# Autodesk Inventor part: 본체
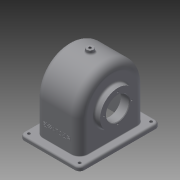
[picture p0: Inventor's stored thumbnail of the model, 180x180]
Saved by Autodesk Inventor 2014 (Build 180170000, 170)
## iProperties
Created: 2016-01
Part Number: 본체
Material: 일반
Document SubType Name: Modeling
Designer: USER
Density: 1 g/cm^3
Appearance: 기본값
Author: USER
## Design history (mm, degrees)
sketch "스케치1"
  geometry: L1 (-57, 0)-(-57, -57); L2 (-57, -57)-(57, -57); L3 (57, 0)-(57, -57); A1 r 57 centre (0, 0) between (57, 0) and (-57, 0); 1 further point
  constraints: 6 end point, 2 perpendicular, 2 point on circle, 2 tangent, 1 centre point, 1 coincident, 1 vertical
  dimensions: "d0" = 114 diameter of A1; "d1" = 57 distance of L1.start L1.end
extrude "돌출1" new body sketch "스케치1" stored distance "d2" = 77; taper "d3" = 0 deg
feature "쉘1" dims "d4" = 6
sketch "스케치3"
  geometry: L1 (0, -51)-(-57, -51) reference; L2 (-57, 51)-(0, 51) reference; L3 (-57, -51)-(-57, 51) reference; A1 r 51 centre (0, 0) between (0, -51) and (0, 51) reference
extrude "돌출2" cut sketch "스케치3" distance "d5" = 1; taper "d6" = 0 deg
sketch "스케치4"
  geometry: L1 (57, -51)-(0, -51) reference; L2 (57, 51)-(57, -51) reference; L3 (0, 51)-(57, 51) reference; A1 r 51 centre (0, 0) between (0, 51) and (0, -51) reference
extrude "돌출3" cut sketch "스케치4" distance "d7" = 1; taper "d8" = 0 deg
sketch "스케치6"
  geometry: L1 (72, -108)-(5, -108) reference; L2 (5, -108)-(5, -6) reference; L3 (5, -6)-(72, -6) reference; L4 (72, -6)-(72, -108) reference; L5 (-13.5, 13)-(90.5, 13); L6 (90.5, 13)-(90.5, -127); L7 (90.5, -127)-(-13.5, -127); L8 (-13.5, -127)-(-13.5, 13); 3 further points
  constraints: 8 end point, 2 midpoint, 2 parallel, 1 horizontal, 1 horizontal alignment, 1 perpendicular, 1 vertical alignment
  dimensions: "d10" = 104 distance between parallel lines of L6 L8; "d11" = 140 distance between parallel lines of L7 L5
extrude "돌출4" join sketch "스케치6" distance "d12" = 7; taper "d13" = 0 deg
sketch "스케치7"
  geometry: C1 r 2.5 at (-5.5, 5); C2 r 2.5 at (82.5, 5); C3 r 2.5 at (-5.5, -119); C4 r 2.5 at (82.5, -119); 1 further point
  constraints: 4 centre point, 2 horizontal alignment, 2 vertical alignment
  dimensions: "d14" = 5 diameter of C1; "d15" = 5 diameter of C2; "d16" = 5 diameter of C3; "d17" = 5 diameter of C4; "d20" = 44 horizontal distance of C2.centre point (38.5, -57); "d21" = 62 vertical distance of point (38.5, -57) C2.centre; "d22" = 124 distance of C4.centre C2.centre; "d23" = 88 distance of C1.centre C2.centre
extrude "돌출5" cut sketch "스케치7" distance "d24" = 7; taper "d25" = 0 deg
fillet "모깎기1" dims "d26" = 14
fillet "모깎기2" dims "d27" = 9
fillet "모깎기3" dims "d28" = 8
node "작업 평면1"
sketch "스케치8"
  geometry: C1 r 6 at (38.5, -57); 1 further point
  constraints: 1 centre point, 1 coincident
  dimensions: "d30" = 12 diameter of C1
extrude "돌출6" join sketch "스케치8" stored distance "d31" = 7; taper "d32" = 0 deg
sketch "스케치9"
  geometry: C1 r 6 at (0, 0) reference; 1 further point
  constraints: 1 coincident
hole "구멍1" sketch "스케치9" at (0, 0) diameter "d33" = 4.459; stored, may be unused: countersink angle "d37" = 90 deg, drill point angle "d39" = 118 deg; dims "d34" = 20, "d35" = 4, "d36" = 2, "d38" = 8
fillet "모깎기4" dims "d40" = 3
sketch "스케치10"
  geometry: L1 (64, 62)-(64, -62) reference; C1 r 31 at (4, 0); A1 r 43 centre (0, 0) between (0, 43) and (0, -43) reference
  constraints: 1 centre point, 1 horizontal alignment
  dimensions: "d41" = 62 diameter of C1; "d42" = 60 distance from line of C1.centre L1
extrude "돌출7" join sketch "스케치10" distance "d43" = 10; taper "d44" = 0 deg
sketch "스케치11"
  geometry: C1 r 31 at (0, 0) reference; C2 r 20 at (0, 0); 1 further point
  constraints: 1 centre point, 1 coincident
  dimensions: "d45" = 40 diameter of C2
extrude "돌출8" cut sketch "스케치11" distance "d46" = 15; taper "d47" = 0 deg
sketch "스케치12"
  geometry: C1 r 20 at (0, 0) reference; 2 further points
  constraints: 1 horizontal alignment
  dimensions: "d48" = 24 distance of C1.centre point (-24, 0)
hole "구멍2" sketch "스케치12" at (-24, 0) diameter "d49" = 2.459; stored, may be unused: countersink angle "d53" = 90 deg, drill point angle "d55" = 118 deg; dims "d50" = 6, "d51" = 4, "d52" = 2, "d54" = 8
node "작업 평면2"
sketch "스케치13"
  geometry: L1 (-64, -42)-(-64, 42) reference; C1 r 28 at (-4, 0); 1 further point
  constraints: 1 centre point, 1 horizontal alignment
  dimensions: "d60" = 56 diameter of C1; "d61" = 60 distance from line of C1.centre L1
extrude "돌출9" join sketch "스케치13" stored distance "d62" = 15; taper "d63" = 40 deg
sketch "스케치15"
  geometry: C1 r 28 at (0, 0) reference; C2 r 20 at (0, 0); 1 further point
  constraints: 1 centre point, 1 coincident
  dimensions: "d64" = 40 diameter of C2
extrude "돌출10" cut sketch "스케치15" distance "d65" = 16; taper "d66" = 0 deg
sketch "스케치16"
  geometry: L1 (38.5, 43)-(38.5, 0) reference; L2 (19.5, 24)-(33.5, 35.747) reference; L3 (35.5, 30.899)-(38.5, 33.416); L4 (35.5, 30.899)-(35.5, -4); L5 (38.5, 33.416)-(38.5, 0); L6 (0, -4)-(66.066, -4); L7 (46.5, -64)-(41.5, -64) reference; L8 (38.5, 0)-(38.5, -57) reference; L9 (35.5, -4)-(38.5, -4); 1 further point
  constraints: 10 end point, 4 point on line, 1 collinear, 1 parallel
  dimensions: "d67" = 5 distance between parallel lines of L2 L3; "d68" = 3 distance between parallel lines of L1 L4; "d69" = 60 distance between parallel lines of L6 L7
revolve "회전1" sketch "스케치16" stored, may be unused: angle "d70" = 90 deg
sketch "스케치17"
  geometry: C1 r 20 at (0, 0) reference; 2 further points
  constraints: 1 vertical alignment
  dimensions: "d71" = 28 distance of C1.centre point (0, 28)
hole "구멍3" sketch "스케치17" at (0, 28) diameter "d72" = 2.459; stored, may be unused: countersink angle "d76" = 90 deg, drill point angle "d78" = 118 deg; dims "d73" = 7, "d74" = 4, "d75" = 2, "d77" = 9
sketch "스케치18"
  geometry: L1 (-14, 0)-(-14, -57) reference; L2 (68.5, -64)-(-19.5, -64) reference; 2 further points
  constraints: 1 other
  dimensions: "d82" = 38.5 distance from line of point (24.5, -34) L1; "d83" = 30 distance from line of L2 point (24.5, -34)
extrude "돌출11" join sketch "스케치18" distance "d84" = 0.5; taper "d85" = 0 deg
fillet "모깎기5" dims "d86" = 3
fillet "모깎기6" dims "d87" = 1
chamfer "모따기1" distance "d88" = 1; stored, may be unused: second distance "d89" = 2, angle "d90" = 45 deg
fillet "모깎기7" dims "d91" = 3
node "솔리드1"
pattern_circular "원형 패턴1" dims angle "d57" = 360 deg
pattern_circular "원형 패턴2" dims angle "d80" = 360 deg
other parameters: "d29" = -127, "d59" = -19
